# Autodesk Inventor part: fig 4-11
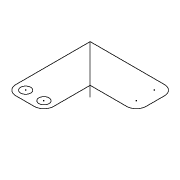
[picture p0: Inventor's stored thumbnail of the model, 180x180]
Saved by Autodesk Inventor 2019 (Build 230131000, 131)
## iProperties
Created: 2005-02
Part Number: fig 4-11
Document SubType Name: Modeling
Designer: CADCIM
Manufacturer: Standard
Standards Organization: Custom
Density: 1 g/cm^3
Material: Generic
Appearance: Default
Author: CADCIM
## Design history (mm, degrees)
sketch "Sketch1"
  geometry: L1 (5.141, 24.979)-(-32.827, 24.979); L2 (-32.827, 24.979)-(-32.827, -12.989); L3 (-27.827, -17.989)-(-18.492, -17.989); L4 (-13.492, -12.989)-(-13.492, 5.644); L5 (-13.492, 5.644)-(5.141, 5.644); L6 (10.141, 10.644)-(10.141, 19.979); L7 (-32.827, 24.979)-(-8.203, 0.354); C1 r 2.58 at (-27.827, -12.989); C2 r 2.58 at (-18.492, -12.989); A1 r 5 centre (-27.827, -12.989) between (-32.827, -12.989) and (-27.827, -17.989); A2 r 5 centre (-18.492, -12.989) between (-18.492, -17.989) and (-13.492, -12.989); A3 r 5 centre (5.141, 10.644) between (5.141, 5.644) and (10.141, 10.644); A4 r 5 centre (5.141, 19.979) between (10.141, 19.979) and (5.141, 24.979)
  constraints: 14 end point, 8 point on circle, 8 tangent, 6 centre point, 4 equal radius, 4 parallel, 3 perpendicular, 2 coincident, 1 horizontal, 1 point on line
